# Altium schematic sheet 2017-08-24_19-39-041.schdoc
size 370 x 127 mm; SheetNumber: 1; SheetTotal: 1
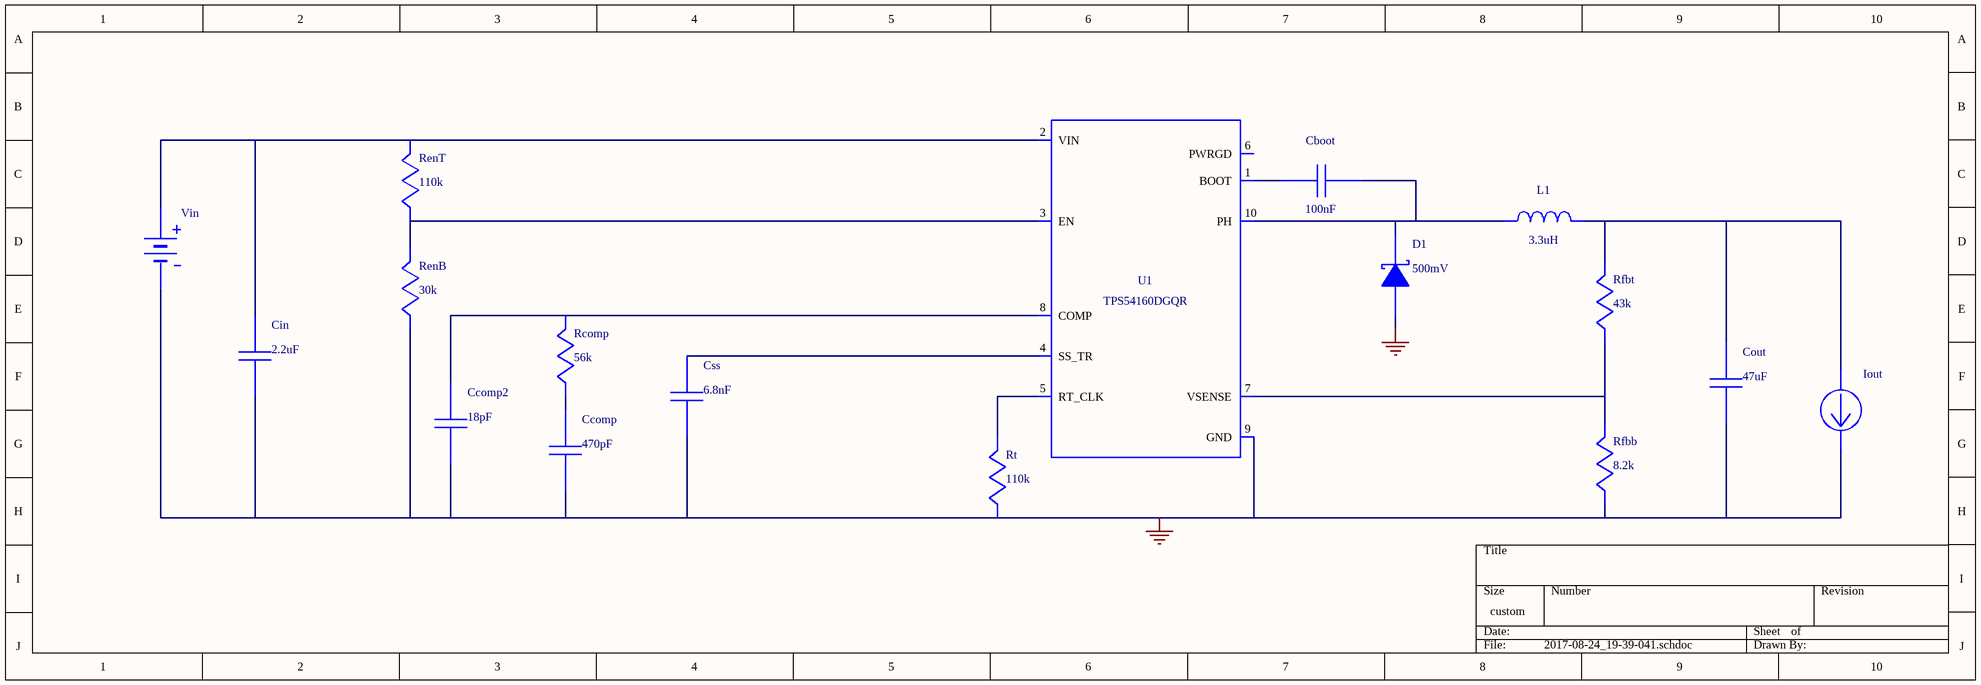
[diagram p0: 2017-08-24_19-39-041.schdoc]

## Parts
Cboot  value 100nF  (hidden comment: GRM155R61A104KA01D)
Ccomp  value 470pF  (hidden comment: CC0805KRX7R9BB471)
Ccomp2  value 18pF  (hidden comment: C0805C180K5GACTU)
Cin  value 2.2uF  (hidden comment: GRM188R61A225KE34D)
Cout  value 47uF  (hidden comment: C2012X5R1A476M125AC)
Css  value 6.8nF  (hidden comment: CC0805KRX7R9BB682)
D1  value 500mV  (hidden comment: B340A-13-F)
Iout  WB_CURRENT_LOAD  (value not drawn)
L1  value 3.3uH  (hidden comment: SRN6045-3R3Y)
Rcomp  value 56k  (hidden comment: RC1206FR-0756KL)
RenB  value 30k  (hidden comment: RC1206FR-0730KL)
RenT  value 110k  (hidden comment: ERJ-8ENF1103V)
Rfbb  value 8.2k  (hidden comment: RC1206FR-078K2L)
Rfbt  value 43k  (hidden comment: RC1206FR-0743KL)
Rt  value 110k  (hidden comment: CRCW1206110KFKEA)
U1  TPS54140DGQR  (value not drawn)
Vin  WB_BATTERY  (value not drawn)

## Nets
0: Ccomp.2 Ccomp2.2 Cin.2 Cout.2 Css.2 D1.2(A) Iout.2(-) RenB.2 Rfbb.2 Rt.2 U1.9(GND) U1.11(EPAD) Vin.2(-)
NetCboot_1: Cboot.1 U1.1(BOOT)
NetCboot_2: Cboot.2 D1.1(K) L1.2 U1.10(PH)
NetCcomp2_1: Ccomp2.1 Rcomp.1 U1.8(COMP)
NetCcomp_1: Ccomp.1 Rcomp.2
NetCin_1: Cin.1 RenT.1 U1.2(VIN) Vin.1(+)
NetCout_1: Cout.1 Iout.1(+) L1.1 Rfbt.1
NetCss_1: Css.1 U1.4(SS_TR)
NetRenB_1: RenB.1 RenT.2 U1.3(EN)
NetRfbb_1: Rfbb.1 Rfbt.2 U1.7(VSENSE)
NetRt_1: Rt.1 U1.5(RT_CLK)

Not connected (* = marked no-connect by the designer): U1 6(PWRGD)

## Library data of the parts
Cboot = GRM155R61A104KA01D: GRM155R61A104KA0; Manufacturer Name: MuRata
Ccomp = CC0805KRX7R9BB471: CC0805KRX7R9BB47; Manufacturer Name: Yageo America
Ccomp2 = C0805C180K5GACTU: Manufacturer Name: Kemet
Cin = GRM188R61A225KE34D: GRM188R61A225KE3; Manufacturer Name: MuRata
Cout = C2012X5R1A476M125AC: C2012X5R1A476M12; Manufacturer Name: TDK
Css = CC0805KRX7R9BB682: CC0805KRX7R9BB68; Manufacturer Name: Yageo America
D1 = B340A-13-F: Manufacturer Name: Diodes Inc.
L1 = SRN6045-3R3Y: Manufacturer Name: Bourns
Rcomp = RC1206FR-0756KL: Manufacturer Name: Yageo America
RenB = RC1206FR-0730KL: Manufacturer Name: Yageo America
RenT = ERJ-8ENF1103V: Manufacturer Name: Panasonic
Rfbb = RC1206FR-078K2L: Manufacturer Name: Yageo America
Rfbt = RC1206FR-0743KL: Manufacturer Name: Yageo America
Rt = CRCW1206110KFKEA: Manufacturer Name: Vishay-Dale
U1 = TPS54140DGQR: TPS54160DGQR; Manufacturer Name: Texas Instruments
